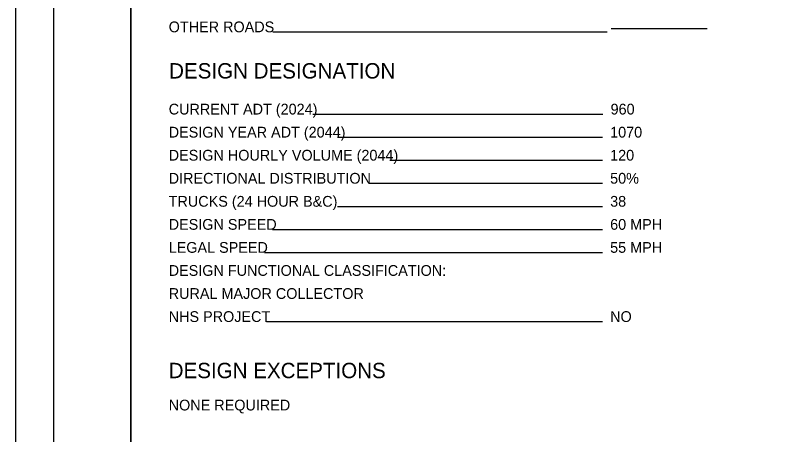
# Model space of a CAD drawing. Extents: x 0 to 34, y 0 to 22.
# Drawn here: x 0 to 9.99, y 5.64 to 11.1 of the extents above; entities that cross this region are included whole.
import ezdxf

# ---------------------------------------------------------------- set-up
doc = ezdxf.new("R2010")
doc.units = 0
for name, color, linetype in [('SH_Border', 7, 'Continuous'), ('SH_Cut_Line', 7, 'Continuous'), ('SH_Data', 7, 'Continuous'), ('SH_Text', 7, 'Continuous')]:
    doc.layers.add(name, color=color, linetype=linetype)

msp = doc.modelspace()

# ---------------------------------------------------------------- linework, layer by layer
at = {"layer": 'SH_Border'}
for points in [[(0.5, 21.5), (1.5, 21.5), (1.5, 0.5), (0.5, 0.5)], [(1.5, 21.5), (33.5, 21.5), (33.5, 0.5), (1.5, 0.5)]]:
    msp.add_lwpolyline(points, close=True, dxfattribs=at)
at = {"layer": 'SH_Cut_Line'}
msp.add_lwpolyline([(0, 0), (34, 0), (34, 22), (0, 22)], close=True, dxfattribs=at)
at = {"layer": 'SH_Data'}
for p, q in [((9, 10.9223), (7.75, 10.9223)), ((7.7, 10.8767), (3.3471, 10.8767)), ((7.6424, 9.8062), (3.871, 9.8062)), ((7.6368, 9.5062), (4.1885, 9.5062)), ((7.6368, 9.2062), (4.8723, 9.2062)), ((7.6368, 8.9062), (4.6037, 8.9062)), ((7.6368, 8.6062), (4.1885, 8.6062)), ((7.6368, 8.3062), (3.346, 8.3062)), ((7.6368, 8.0062), (3.2422, 8.0062)), ((7.6368, 7.1062), (3.2669, 7.1062))]:
    msp.add_line(p, q, dxfattribs=at)

# ---------------------------------------------------------------- texts
msp.add_text('DESIGN DESIGNATION', height=0.2, dxfattribs=at).set_placement((2, 10.2747))
at = {"layer": 'SH_Text'}
for s, height, p in [('OTHER ROADS', 0.14, (1.9944, 10.8767)), ('CURRENT ADT (2024)', 0.14, (1.9944, 9.8062)), ('960', 0.14, (7.7424, 9.8062)), ('DESIGN YEAR ADT (2044)', 0.14, (1.9944, 9.5062)), ('1070', 0.14, (7.7368, 9.5062)), ('DESIGN HOURLY VOLUME (2044)', 0.14, (1.9944, 9.2062)), ('120', 0.14, (7.7368, 9.2062)), ('DIRECTIONAL DISTRIBUTION', 0.14, (1.9944, 8.9062)), ('50%', 0.14, (7.7368, 8.9062)), ('TRUCKS (24 HOUR B&C)', 0.14, (1.9944, 8.6062)), ('38', 0.14, (7.7368, 8.6062)), ('DESIGN SPEED', 0.14, (1.9944, 8.3062)), ('60 MPH', 0.14, (7.7368, 8.3062)), ('LEGAL SPEED', 0.14, (1.9944, 8.0062)), ('55 MPH', 0.14, (7.7368, 8.0062)), ('DESIGN FUNCTIONAL CLASSIFICATION:', 0.14, (1.9944, 7.7062)), ('RURAL MAJOR COLLECTOR', 0.14, (1.9944, 7.4062)), ('NHS PROJECT', 0.14, (1.9944, 7.1062)), ('NO', 0.14, (7.7368, 7.1062)), ('DESIGN EXCEPTIONS', 0.2, (1.9944, 6.3744)), ('NONE REQUIRED', 0.14, (1.9944, 5.9544))]:
    msp.add_text(s, height=height, dxfattribs=at).set_placement(p)

doc.saveas('drawing.dxf')
